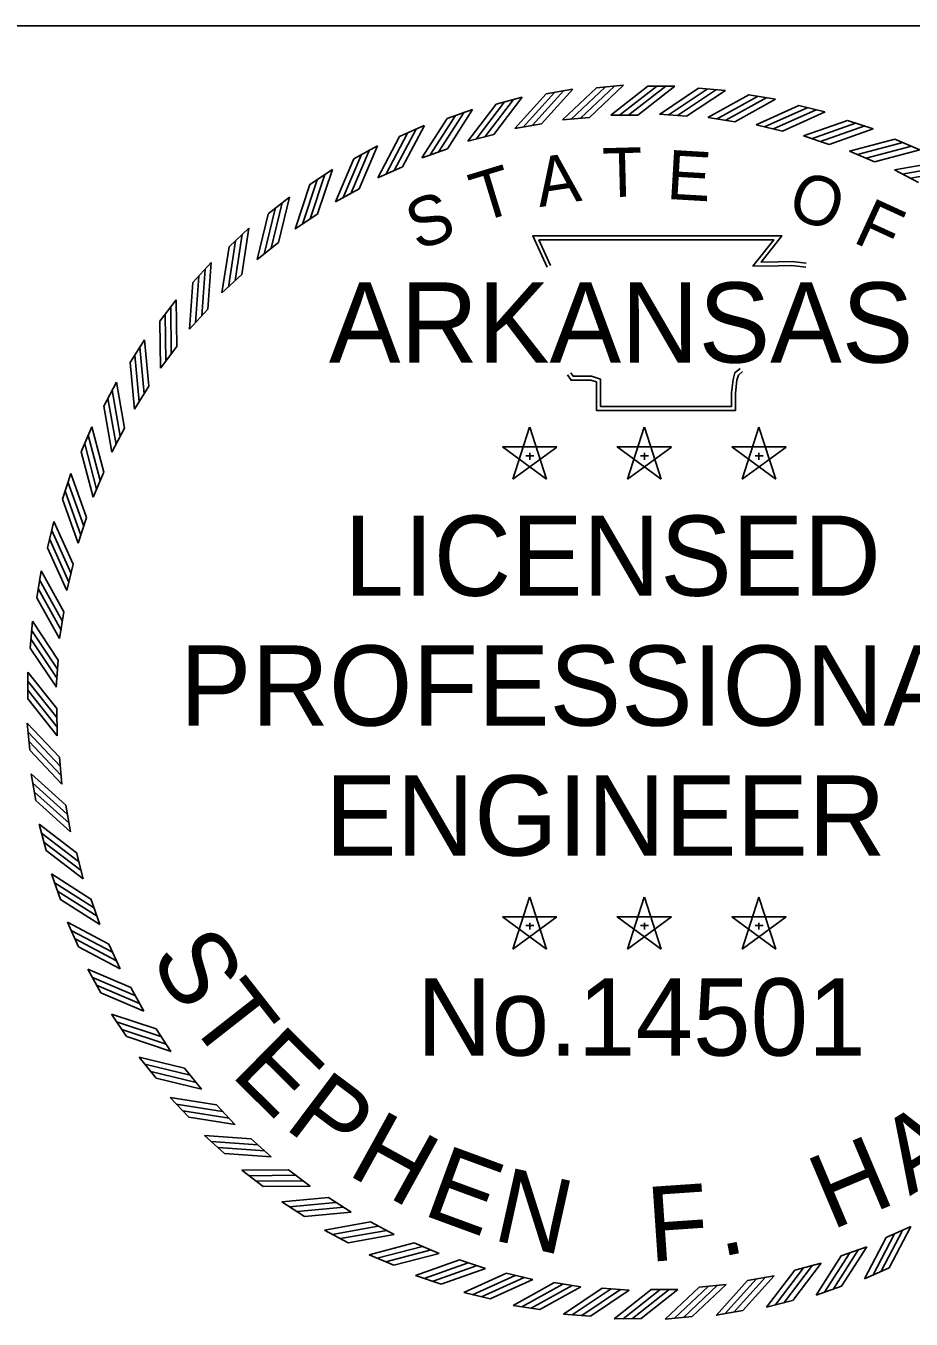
# Model space of a CAD drawing. Extents: x 16 to 1228740, y 11 to 152440.
# Drawn here: x 17.6747 to 17.7982, y 10.8182 to 10.9986 of the extents above; entities that cross this region are included whole.
import ezdxf

# ---------------------------------------------------------------- set-up
doc = ezdxf.new("R2010")
doc.units = 0
doc.layers.add('R_No Plot', color=7, linetype='Continuous')
doc.layers.add('STAMP_FRED', color=7, linetype='Continuous')

msp = doc.modelspace()

# ---------------------------------------------------------------- linework, layer by layer
at = {"layer": 'R_No Plot'}
msp.add_line((17.888, 10.99864), (17.47349, 10.99864), dxfattribs=at)
at = {"layer": 'STAMP_FRED'}
for p, q in [((17.75431, 10.98999), (17.75806, 10.99034)), ((17.74029, 10.98773), (17.74393, 10.98868)), ((17.74725, 10.98915), (17.75096, 10.9898)), ((17.76145, 10.9902), (17.76522, 10.9902)), ((17.76851, 10.98992), (17.77227, 10.98964)), ((17.77555, 10.989), (17.77928, 10.98842)), ((17.73347, 10.98573), (17.73702, 10.98699)), ((17.7825, 10.98751), (17.78616, 10.98662)), ((17.74288, 10.9843), (17.7466, 10.98496)), ((17.74955, 10.98553), (17.75332, 10.98587)), ((17.7563, 10.98619), (17.76008, 10.98619)), ((17.76308, 10.9863), (17.76685, 10.98602)), ((17.76985, 10.98584), (17.77358, 10.98525)), ((17.7893, 10.98545), (17.79288, 10.98426)), ((17.72683, 10.98318), (17.73027, 10.98473)), ((17.73633, 10.98254), (17.73999, 10.9835)), ((17.77655, 10.98483), (17.78023, 10.98394)), ((17.78315, 10.98327), (17.78674, 10.98207)), ((17.72043, 10.9801), (17.72373, 10.98192)), ((17.72996, 10.98024), (17.73352, 10.9815)), ((17.79591, 10.98283), (17.79938, 10.98135)), ((17.7896, 10.98117), (17.79308, 10.97968)), ((17.71431, 10.97649), (17.71745, 10.97858)), ((17.72379, 10.97742), (17.72723, 10.97896)), ((17.79585, 10.97854), (17.79919, 10.97677)), ((17.71787, 10.97409), (17.72118, 10.97592)), ((17.70851, 10.97239), (17.71146, 10.97473)), ((17.71226, 10.9703), (17.7154, 10.97239)), ((17.70306, 10.96782), (17.70581, 10.9704)), ((17.70697, 10.96605), (17.70993, 10.9684)), ((17.69801, 10.96283), (17.70054, 10.96562)), ((17.70205, 10.96138), (17.70481, 10.96396)), ((17.69339, 10.95743), (17.69568, 10.96042)), ((17.69754, 10.95632), (17.70007, 10.95912)), ((17.68923, 10.95166), (17.69126, 10.95484)), ((17.69346, 10.9509), (17.69575, 10.95391)), ((17.68556, 10.94558), (17.68733, 10.94891)), ((17.68984, 10.94517), (17.69187, 10.94835)), ((17.68241, 10.93921), (17.68389, 10.94268)), ((17.6867, 10.93915), (17.68847, 10.94249)), ((17.74497, 10.94264), (17.74261, 10.9354)), ((17.74732, 10.93541), (17.74498, 10.94265)), ((17.76096, 10.94264), (17.7586, 10.9354)), ((17.76331, 10.93541), (17.76097, 10.94265)), ((17.77695, 10.94264), (17.77459, 10.9354)), ((17.7793, 10.93541), (17.77696, 10.94265)), ((17.74877, 10.93988), (17.74116, 10.93988)), ((17.74117, 10.93988), (17.74732, 10.9354)), ((17.74262, 10.93541), (17.74878, 10.93987)), ((17.76476, 10.93988), (17.75715, 10.93988)), ((17.75716, 10.93988), (17.76331, 10.9354)), ((17.75861, 10.93541), (17.76477, 10.93987)), ((17.78076, 10.93988), (17.77315, 10.93988)), ((17.77315, 10.93988), (17.7793, 10.9354)), ((17.7746, 10.93541), (17.78076, 10.93987)), ((17.74443, 10.93866), (17.74556, 10.93866)), ((17.74498, 10.93907), (17.74498, 10.93811)), ((17.76042, 10.93866), (17.76155, 10.93866)), ((17.76097, 10.93907), (17.76097, 10.93811)), ((17.77641, 10.93866), (17.77754, 10.93866)), ((17.77696, 10.93907), (17.77696, 10.93811)), ((17.67979, 10.9326), (17.68098, 10.93618)), ((17.68407, 10.9329), (17.68556, 10.93638)), ((17.67773, 10.9258), (17.67862, 10.92947)), ((17.68197, 10.92645), (17.68317, 10.93004)), ((17.68041, 10.91985), (17.6813, 10.92353)), ((17.67624, 10.91885), (17.67682, 10.92258)), ((17.6794, 10.91315), (17.67999, 10.91688)), ((17.67532, 10.91181), (17.6756, 10.91557)), ((17.67894, 10.90638), (17.67922, 10.91015)), ((17.67499, 10.90471), (17.67496, 10.90848)), ((17.67905, 10.8996), (17.67902, 10.90338)), ((17.67525, 10.89761), (17.6749, 10.90136)), ((17.67972, 10.89285), (17.67937, 10.89662)), ((17.67609, 10.89055), (17.67544, 10.89426)), ((17.68094, 10.88618), (17.68028, 10.8899)), ((17.67751, 10.88359), (17.67656, 10.88724)), ((17.6827, 10.87963), (17.68174, 10.88329)), ((17.67951, 10.87677), (17.67825, 10.88032)), ((17.685, 10.87326), (17.68375, 10.87682)), ((17.74497, 10.87707), (17.74261, 10.86984)), ((17.74732, 10.86984), (17.74498, 10.87708)), ((17.76096, 10.87707), (17.7586, 10.86984)), ((17.76331, 10.86984), (17.76097, 10.87708)), ((17.77695, 10.87707), (17.77459, 10.86984)), ((17.7793, 10.86984), (17.77696, 10.87708)), ((17.68206, 10.87014), (17.68051, 10.87357)), ((17.74877, 10.87431), (17.74116, 10.87432)), ((17.74117, 10.87431), (17.74732, 10.86983)), ((17.74262, 10.86984), (17.74878, 10.87431)), ((17.74443, 10.8731), (17.74556, 10.8731)), ((17.74498, 10.8735), (17.74498, 10.87255)), ((17.76476, 10.87431), (17.75715, 10.87432)), ((17.75716, 10.87431), (17.76331, 10.86983)), ((17.75861, 10.86984), (17.76477, 10.87431)), ((17.76042, 10.8731), (17.76155, 10.8731)), ((17.76097, 10.8735), (17.76097, 10.87255)), ((17.78076, 10.87431), (17.77315, 10.87432)), ((17.77315, 10.87431), (17.7793, 10.86983)), ((17.7746, 10.86984), (17.78076, 10.87431)), ((17.77641, 10.8731), (17.77754, 10.8731)), ((17.77696, 10.8735), (17.77696, 10.87255)), ((17.68783, 10.86709), (17.68628, 10.87053)), ((17.68515, 10.86374), (17.68332, 10.86703)), ((17.69115, 10.86118), (17.68932, 10.86448)), ((17.68875, 10.85761), (17.68666, 10.86075)), ((17.69494, 10.85556), (17.69285, 10.8587)), ((17.69285, 10.85181), (17.69051, 10.85476)), ((17.69919, 10.85027), (17.69684, 10.85323)), ((17.69742, 10.84636), (17.69484, 10.84911)), ((17.70386, 10.84535), (17.70128, 10.84811)), ((17.70242, 10.84131), (17.69962, 10.84384)), ((17.70892, 10.84084), (17.70612, 10.84337)), ((17.70781, 10.83669), (17.70482, 10.83898)), ((17.71434, 10.83676), (17.71134, 10.83905)), ((17.72007, 10.83314), (17.71689, 10.83517)), ((17.71358, 10.83253), (17.7104, 10.83456)), ((17.72609, 10.83), (17.72275, 10.83177)), ((17.71966, 10.82886), (17.71633, 10.83063)), ((17.79815, 10.83113), (17.79471, 10.82958)), ((17.73234, 10.82738), (17.72886, 10.82886)), ((17.79199, 10.82831), (17.78842, 10.82705)), ((17.72603, 10.82571), (17.72257, 10.82719)), ((17.73879, 10.82527), (17.7352, 10.82647)), ((17.74539, 10.82371), (17.74171, 10.82461)), ((17.78561, 10.826), (17.78195, 10.82504)), ((17.79511, 10.82536), (17.79167, 10.82381)), ((17.73264, 10.82309), (17.72906, 10.82428)), ((17.75209, 10.8227), (17.74836, 10.82329)), ((17.75886, 10.82224), (17.75509, 10.82252)), ((17.77239, 10.82302), (17.76863, 10.82267)), ((17.77906, 10.82424), (17.77534, 10.82358)), ((17.78847, 10.82281), (17.78492, 10.82155)), ((17.73944, 10.82103), (17.73578, 10.82192)), ((17.76564, 10.82235), (17.76186, 10.82232)), ((17.78165, 10.82082), (17.77801, 10.81986)), ((17.74639, 10.81954), (17.74266, 10.82012)), ((17.75343, 10.81862), (17.74967, 10.8189)), ((17.77469, 10.81939), (17.77098, 10.81874)), ((17.76053, 10.81829), (17.75676, 10.81826)), ((17.76763, 10.81855), (17.76388, 10.8182))]:
    msp.add_line(p, q, dxfattribs=at)
for points in [[(17.75331, 10.98587), (17.75806, 10.99034)], [(17.73998, 10.9835), (17.74394, 10.98869)], [(17.74288, 10.9843), (17.74725, 10.98914)], [(17.74407, 10.9845), (17.74844, 10.98934)], [(17.74536, 10.98476), (17.74973, 10.9896)], [(17.7466, 10.98496), (17.75097, 10.98981)], [(17.74955, 10.98552), (17.7543, 10.98999)], [(17.75076, 10.98562), (17.75551, 10.99009)], [(17.75206, 10.98577), (17.75681, 10.99024)], [(17.7563, 10.98619), (17.76144, 10.9902)], [(17.75751, 10.98618), (17.76265, 10.99019)], [(17.75882, 10.9862), (17.76396, 10.99022)], [(17.76008, 10.98619), (17.76522, 10.9902)], [(17.76308, 10.98629), (17.7685, 10.98992)], [(17.76429, 10.98619), (17.76971, 10.98982)], [(17.7656, 10.98613), (17.77102, 10.98975)], [(17.76685, 10.98602), (17.77227, 10.98964)], [(17.76984, 10.98584), (17.77555, 10.989)], [(17.77104, 10.98564), (17.77675, 10.9888)], [(17.77234, 10.98546), (17.77804, 10.98863)], [(17.73351, 10.9815), (17.73702, 10.98699)], [(17.73633, 10.98253), (17.74028, 10.98772)], [(17.73751, 10.98283), (17.74146, 10.98802)], [(17.73877, 10.98319), (17.74272, 10.98838)], [(17.77358, 10.98526), (17.77928, 10.98842)], [(17.77655, 10.98483), (17.7825, 10.98751)], [(17.77773, 10.98453), (17.78367, 10.98721)], [(17.779, 10.98425), (17.78495, 10.98693)], [(17.72995, 10.98023), (17.73346, 10.98573)], [(17.7311, 10.98063), (17.73461, 10.98612)], [(17.73232, 10.98109), (17.73584, 10.98659)], [(17.78022, 10.98394), (17.78617, 10.98662)], [(17.78315, 10.98327), (17.7893, 10.98545)], [(17.7843, 10.98287), (17.79044, 10.98505)], [(17.72379, 10.97741), (17.72683, 10.98318)], [(17.7249, 10.9779), (17.72794, 10.98367)], [(17.72608, 10.97846), (17.72912, 10.98423)], [(17.72723, 10.97897), (17.73028, 10.98473)], [(17.78555, 10.98249), (17.7917, 10.98467)], [(17.78674, 10.98208), (17.79288, 10.98426)], [(17.72007, 10.97533), (17.72263, 10.98133)], [(17.72118, 10.97592), (17.72374, 10.98192)], [(17.7896, 10.98116), (17.7959, 10.98283)], [(17.79071, 10.98068), (17.79701, 10.98234)], [(17.79192, 10.98019), (17.79823, 10.98185)], [(17.79307, 10.97968), (17.79938, 10.98135)], [(17.71787, 10.97409), (17.72043, 10.98009)], [(17.71894, 10.97467), (17.7215, 10.98067)], [(17.79585, 10.97854), (17.80227, 10.97968)], [(17.71434, 10.97171), (17.7164, 10.9779)], [(17.71539, 10.97239), (17.71745, 10.97858)], [(17.79692, 10.97796), (17.80334, 10.9791)], [(17.79809, 10.97737), (17.80451, 10.97851)], [(17.71225, 10.97029), (17.71431, 10.97648)], [(17.71327, 10.97096), (17.71532, 10.97715)], [(17.70992, 10.9684), (17.71146, 10.97474)], [(17.70697, 10.96604), (17.70851, 10.97238)], [(17.70793, 10.96679), (17.70946, 10.97313)], [(17.70893, 10.96763), (17.71047, 10.97396)], [(17.70294, 10.9622), (17.70395, 10.96864)], [(17.70388, 10.96311), (17.70489, 10.96956)], [(17.7048, 10.96396), (17.70581, 10.97041)], [(17.7474, 10.96497), (17.74539, 10.96932), (17.78016, 10.96934), (17.77725, 10.96569), (17.77962, 10.96572), (17.78159, 10.96575), (17.78356, 10.96553)], [(17.7479, 10.9652), (17.74625, 10.96877), (17.77902, 10.96879), (17.7761, 10.96513), (17.77962, 10.96517), (17.78156, 10.9652), (17.7835, 10.96499)], [(17.70205, 10.96137), (17.70306, 10.96782)], [(17.70007, 10.95912), (17.70054, 10.96563)], [(17.69836, 10.95721), (17.69883, 10.96371)], [(17.69922, 10.9582), (17.69969, 10.9647)], [(17.69754, 10.95631), (17.69801, 10.96282)], [(17.69574, 10.9539), (17.69568, 10.96043)], [(17.6942, 10.95185), (17.69414, 10.95838)], [(17.69497, 10.95291), (17.69491, 10.95944)], [(17.69346, 10.9509), (17.69339, 10.95742)], [(17.69187, 10.94835), (17.69126, 10.95484)], [(17.6905, 10.94618), (17.6899, 10.95267)], [(17.69118, 10.9473), (17.69058, 10.95379)], [(17.68984, 10.94516), (17.68923, 10.95166)], [(17.77433, 10.95083), (17.7736, 10.95023), (17.77335, 10.9493), (17.77314, 10.94742), (17.77314, 10.94554), (17.75484, 10.94554), (17.75484, 10.94824), (17.75484, 10.94936), (17.75358, 10.94975), (17.75104, 10.94975), (17.75071, 10.95025)], [(17.68847, 10.94249), (17.68733, 10.94891)], [(17.77468, 10.9504), (17.77409, 10.94992), (17.77389, 10.9492), (17.77369, 10.94739), (17.77369, 10.94499), (17.75429, 10.94499), (17.75429, 10.94824), (17.75429, 10.94896), (17.7535, 10.9492), (17.75074, 10.9492), (17.75025, 10.94995)], [(17.68787, 10.94139), (17.68673, 10.94781)], [(17.6867, 10.93915), (17.68556, 10.94557)], [(17.68728, 10.94022), (17.68614, 10.94664)], [(17.68556, 10.93637), (17.68389, 10.94268)], [(17.68456, 10.93401), (17.6829, 10.94031)], [(17.68505, 10.93522), (17.68339, 10.94153)], [(17.68408, 10.9329), (17.68241, 10.9392)], [(17.68316, 10.93004), (17.68098, 10.93618)], [(17.68276, 10.92885), (17.68057, 10.935)], [(17.68197, 10.92645), (17.67979, 10.9326)], [(17.68237, 10.9276), (17.68019, 10.93374)], [(17.6813, 10.92352), (17.67862, 10.92947)], [(17.68099, 10.92231), (17.67831, 10.92825)], [(17.68041, 10.91985), (17.67773, 10.9258)], [(17.68071, 10.92103), (17.67803, 10.92697)], [(17.67998, 10.91688), (17.67682, 10.92258)], [(17.6796, 10.91434), (17.67644, 10.92005)], [(17.67978, 10.91564), (17.67661, 10.92134)], [(17.6794, 10.91314), (17.67624, 10.91885)], [(17.67922, 10.91015), (17.6756, 10.91557)], [(17.67905, 10.90759), (17.67542, 10.91301)], [(17.67912, 10.9089), (17.67549, 10.91432)], [(17.67895, 10.90638), (17.67532, 10.9118)], [(17.67901, 10.90338), (17.67495, 10.90848)], [(17.67901, 10.90212), (17.67495, 10.90723)], [(17.67905, 10.90081), (17.675, 10.90592)], [(17.67905, 10.8996), (17.675, 10.9047)], [(17.67937, 10.89661), (17.6749, 10.90136)], [(17.67947, 10.89536), (17.675, 10.90011)], [(17.67962, 10.89406), (17.67515, 10.89881)], [(17.67972, 10.89285), (17.67525, 10.8976)], [(17.68028, 10.8899), (17.67543, 10.89427)], [(17.68048, 10.88866), (17.67564, 10.89303)], [(17.68074, 10.88738), (17.6759, 10.89174)], [(17.68094, 10.88618), (17.6761, 10.89055)], [(17.68174, 10.88328), (17.67655, 10.88724)], [(17.68205, 10.88207), (17.67686, 10.88602)], [(17.68241, 10.88081), (17.67722, 10.88476)], [(17.68271, 10.87963), (17.67752, 10.88359)], [(17.68374, 10.87681), (17.67825, 10.88032)], [(17.68415, 10.87563), (17.67865, 10.87914)], [(17.68462, 10.8744), (17.67912, 10.87791)], [(17.68501, 10.87325), (17.67951, 10.87676)], [(17.68628, 10.87053), (17.68051, 10.87358)], [(17.68678, 10.86938), (17.68101, 10.87243)], [(17.68734, 10.8682), (17.68158, 10.87124)], [(17.68783, 10.86709), (17.68206, 10.87013)], [(17.68932, 10.86448), (17.68332, 10.86704)], [(17.68991, 10.86337), (17.68391, 10.86593)], [(17.69057, 10.86224), (17.68457, 10.8648)], [(17.69115, 10.86117), (17.68515, 10.86373)], [(17.69285, 10.8587), (17.68666, 10.86075)], [(17.69353, 10.85764), (17.68734, 10.8597)], [(17.69428, 10.85657), (17.68809, 10.85863)], [(17.69495, 10.85555), (17.68876, 10.85761)], [(17.69684, 10.85323), (17.6905, 10.85476)], [(17.69762, 10.85223), (17.69128, 10.85377)], [(17.69845, 10.85123), (17.69211, 10.85276)], [(17.6992, 10.85027), (17.69286, 10.85181)], [(17.70128, 10.8481), (17.69483, 10.84911)], [(17.70213, 10.84718), (17.69568, 10.84819)], [(17.70305, 10.84624), (17.6966, 10.84725)], [(17.70387, 10.84535), (17.69742, 10.84636)], [(17.70612, 10.84337), (17.69961, 10.84384)], [(17.70704, 10.84252), (17.70054, 10.84299)], [(17.70804, 10.84166), (17.70153, 10.84213)], [(17.70893, 10.84084), (17.70242, 10.84131)], [(17.71134, 10.83905), (17.70481, 10.83898)], [(17.71233, 10.83827), (17.70581, 10.83821)], [(17.71339, 10.8375), (17.70686, 10.83744)], [(17.71434, 10.83676), (17.70782, 10.83669)], [(17.71689, 10.83517), (17.7104, 10.83456)], [(17.71794, 10.83448), (17.71145, 10.83388)], [(17.71906, 10.8338), (17.71257, 10.8332)], [(17.72008, 10.83314), (17.71358, 10.83253)], [(17.72275, 10.83177), (17.71633, 10.83063)], [(17.72385, 10.83117), (17.71743, 10.83003)], [(17.72503, 10.83058), (17.7186, 10.82944)], [(17.72609, 10.83), (17.71967, 10.82886)], [(17.79586, 10.83008), (17.79282, 10.82431)], [(17.79704, 10.83064), (17.794, 10.82488)], [(17.79816, 10.83113), (17.79511, 10.82536)], [(17.72887, 10.82886), (17.72256, 10.82719)], [(17.73002, 10.82835), (17.72371, 10.82669)], [(17.79084, 10.82792), (17.78733, 10.82242)], [(17.79199, 10.82831), (17.78848, 10.82281)], [(17.79471, 10.82958), (17.79167, 10.82381)], [(17.73123, 10.82786), (17.72493, 10.8262)], [(17.73234, 10.82738), (17.72604, 10.82571)], [(17.7352, 10.82646), (17.72906, 10.82428)], [(17.78843, 10.82704), (17.78492, 10.82155)], [(17.78962, 10.82745), (17.7861, 10.82196)], [(17.73639, 10.82606), (17.73025, 10.82387)], [(17.73764, 10.82567), (17.7315, 10.82349)], [(17.73879, 10.82528), (17.73264, 10.82309)], [(17.74172, 10.8246), (17.73577, 10.82192)], [(17.74294, 10.82429), (17.73699, 10.82161)], [(17.78196, 10.82504), (17.778, 10.81985)], [(17.78317, 10.82535), (17.77922, 10.82016)], [(17.78443, 10.82571), (17.78048, 10.82052)], [(17.78561, 10.82601), (17.78166, 10.82082)], [(17.74421, 10.82401), (17.73827, 10.82133)], [(17.74539, 10.82371), (17.73944, 10.82103)], [(17.74836, 10.82328), (17.74266, 10.82012)], [(17.7496, 10.82308), (17.7439, 10.81991)], [(17.7509, 10.8229), (17.74519, 10.81974)], [(17.7521, 10.8227), (17.74639, 10.81954)], [(17.75509, 10.82252), (17.74967, 10.8189)], [(17.76863, 10.82267), (17.76388, 10.8182)], [(17.76988, 10.82277), (17.76513, 10.8183)], [(17.77118, 10.82292), (17.76643, 10.81845)], [(17.77239, 10.82302), (17.76764, 10.81855)], [(17.77534, 10.82358), (17.77097, 10.81873)], [(17.77658, 10.82379), (17.77221, 10.81894)], [(17.77787, 10.82404), (17.7735, 10.8192)], [(17.77906, 10.82424), (17.77469, 10.8194)], [(17.75635, 10.82242), (17.75092, 10.81879)], [(17.75765, 10.82235), (17.75223, 10.81873)], [(17.75886, 10.82225), (17.75344, 10.81862)], [(17.76186, 10.82231), (17.75676, 10.81825)], [(17.76312, 10.82231), (17.75801, 10.81825)], [(17.76443, 10.82235), (17.75932, 10.8183)], [(17.76564, 10.82235), (17.76054, 10.8183)]]:
    msp.add_lwpolyline(points, dxfattribs=at)

# ---------------------------------------------------------------- texts
for s, height, rotation, p in [('T', 0.00686, 1.4789, (17.7552, 10.97471)), ('E', 0.00686, 356.672, (17.76397, 10.9745)), ('A', 0.00686, 8.6788, (17.74634, 10.97334)), ('T', 0.00686, 16.9015, (17.73801, 10.97117)), ('O', 0.00686, 341.2218, (17.78063, 10.97215)), ('S', 0.00686, 19.7726, (17.72929, 10.96725)), ('F', 0.00686, 335.3628, (17.78987, 10.96853)), ('S', 0.01042, 300.7985, (17.69188, 10.86863)), ('T', 0.01042, 308.0945, (17.69697, 10.8601)), ('E', 0.01042, 315.3905, (17.7031, 10.85228)), ('P', 0.01042, 323.0513, (17.71054, 10.84498)), ('H', 0.01042, 331.0769, (17.71932, 10.83847)), ('A', 0.01042, 31.6338, (17.79797, 10.83533)), ('H', 0.01042, 22.8786, (17.78705, 10.83056)), ('E', 0.01042, 339.8321, (17.72982, 10.83284)), ('N', 0.01042, 347.4929, (17.73962, 10.82928)), ('F', 0.01042, 3.9089, (17.7617, 10.8262)), ('.', 0.01042, 11.205, (17.77161, 10.82688))]:
    msp.add_text(s, height=height, rotation=rotation, dxfattribs=at).set_placement(p)
for s, height, p in [('ARKANSAS', 0.011193, (17.71697, 10.95165)), ('LICENSED', 0.011193, (17.7191, 10.91912)), ('PROFESSIONAL', 0.0111934, (17.69618, 10.901)), ('ENGINEER', 0.011193, (17.71644, 10.88287)), ('No.14501', 0.010794, (17.72924, 10.85496))]:
    msp.add_text(s, height=height, dxfattribs=at).set_placement(p)

doc.saveas('drawing.dxf')
